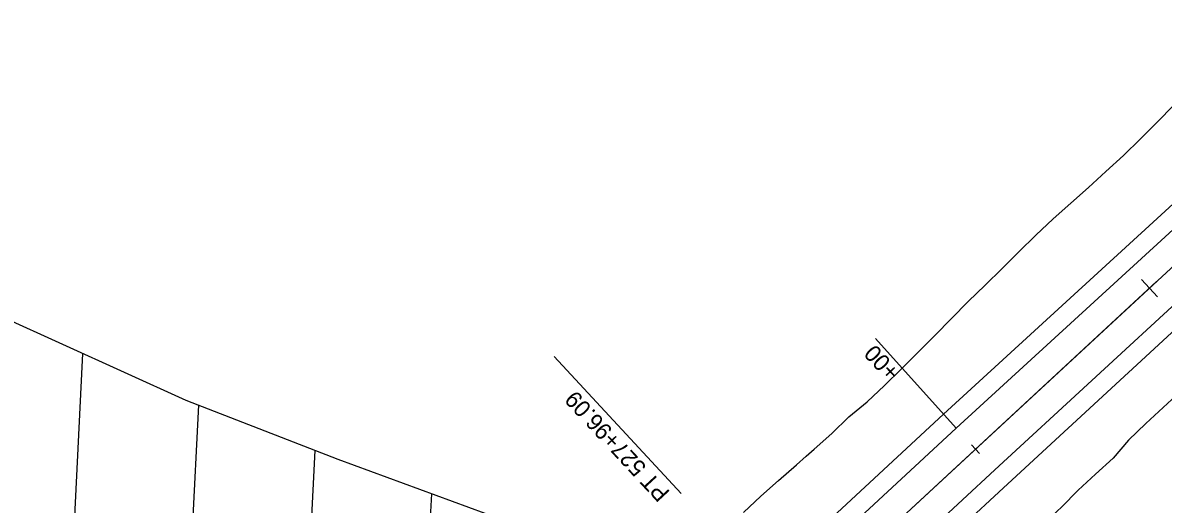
# Model space of a CAD drawing. Extents: x 1300404 to 1323571, y 237813 to 252077.
# Drawn here: x 1311040.8 to 1311522.1, y 242089.5 to 242292.7 of the extents above; entities that cross this region are included whole.
import ezdxf

# ---------------------------------------------------------------- set-up
doc = ezdxf.new("R2010")
doc.units = 0
for name, color, linetype in [('R_Const Limits', 7, 'Continuous'), ('R_Floodway', 7, 'Continuous'), ('R_Horz Alg Annot', 7, 'Continuous'), ('R_Horz Alg Annot Leader', 7, 'Continuous'), ('R_Horz Alg Major Ticks', 7, 'Continuous'), ('R_Horz Alg Minor Ticks', 7, 'Continuous'), ('R_Lane Edge', 7, 'Continuous'), ('R_Proposed', 7, 'Continuous'), ('R_Shoulder', 7, 'Continuous')]:
    doc.layers.add(name, color=color, linetype=linetype)

msp = doc.modelspace()

# ---------------------------------------------------------------- linework, layer by layer
at = {"layer": 'R_Const Limits'}
for points in [[(1311345.07, 242085.98), (1311352.3, 242092.89), (1311359.8, 242099.51), (1311367.33, 242106.09), (1311371.51, 242109.76), (1311374.89, 242112.65), (1311382.3, 242119.36), (1311389.43, 242126.38), (1311397.19, 242132.72), (1311404.48, 242139.57), (1311411.63, 242146.56), (1311418.68, 242153.67), (1311425.77, 242160.72), (1311432.82, 242167.83), (1311439.84, 242174.97), (1311447, 242181.96), (1311454.13, 242188.98), (1311461.27, 242195.98), (1311468.41, 242202.99), (1311475.66, 242209.88), (1311483.09, 242216.57), (1311490.56, 242223.22), (1311497.97, 242229.94), (1311505.4, 242236.63), (1311512.52, 242243.67), (1311519.54, 242250.8), (1311526.59, 242257.9)], [(1311529.44, 242137.05), (1311522.06, 242130.31), (1311514.74, 242123.5), (1311507.54, 242116.56), (1311500.96, 242108.95), (1311493.6, 242102.17), (1311486.31, 242095.33), (1311479.28, 242088.2), (1311471.89, 242081.46), (1311465.07, 242074.11), (1311457.65, 242067.4), (1311450.85, 242060.03), (1311443.97, 242052.74), (1311437.27, 242045.26), (1311434.66, 242041.54), (1311430.29, 242038.08), (1311422.46, 242031.81), (1311413.34, 242026.95), (1311405.41, 242020.79), (1311295.28, 241916.73), (1311295.28, 241916.73)]]:
    msp.add_lwpolyline(points, dxfattribs=at)
at = {"layer": 'R_Floodway'}
for p, q in [((1311041.47, 241659.98), (1311066.18, 242153.15)), ((1311090.32, 241635.77), (1311115.15, 242131.3)), ((1311139.11, 241610.32), (1311164.25, 242112.14)), ((1311187.9, 241584.88), (1311213.4, 242093.9))]:
    msp.add_line(p, q, dxfattribs=at)
msp.add_lwpolyline([(1310379.63, 242680.75), (1310490.18, 242568.72), (1310548.96, 242534.3), (1310676.05, 242414.18), (1310731.56, 242362.99), (1310810.26, 242291.28), (1310887.62, 242241.41), (1310974.87, 242195.88), (1311031.59, 242168.82), (1311109.67, 242133.43), (1311173.76, 242108.43), (1311242.66, 242083.18), (1311339.33, 242032.34), (1311351.04, 242024.49), (1311431.54, 241940.59), (1311405.15, 241750.77), (1311416.02, 241677.63), (1311441.14, 241598.94), (1311547.83, 241506.46), (1311691.44, 241475.03), (1311836.73, 241477.39), (1311974.41, 241472.87)], dxfattribs=at)
at = {"layer": 'R_Horz Alg Annot Leader'}
for points in [[(1311400.69, 242159.47), (1311434.79, 242121.54)], [(1311318.65, 242094.04), (1311265.15, 242151.83)]]:
    msp.add_lwpolyline(points, dxfattribs=at)
at = {"layer": 'R_Horz Alg Major Ticks'}
msp.add_lwpolyline([(1311512.93, 242184.34), (1311519.72, 242177)], dxfattribs=at)
at = {"layer": 'R_Horz Alg Minor Ticks'}
msp.add_lwpolyline([(1311441.24, 242114.57), (1311444.64, 242110.9)], dxfattribs=at)
at = {"layer": 'R_Lane Edge'}
for p, q in [((1311434.79, 242121.54), (1311582.2, 242256.72)), ((1311451.09, 242103.93), (1311598.05, 242239.59)), ((1311434.79, 242121.54), (1311358.53, 242050.95)), ((1311451.09, 242103.93), (1311374.83, 242033.34))]:
    msp.add_line(p, q, dxfattribs=at)
at = {"layer": 'R_Proposed'}
for p, q in [((1311366.68, 242042.15), (1311685.11, 242336.91)), ((1311519.37, 242183.49), (1311366.68, 242042.15)), ((1311366.68, 242042.15), (1311519.37, 242183.49)), ((1311366.68, 242042.15), (1311519.37, 242183.49))]:
    msp.add_line(p, q, dxfattribs=at)
at = {"layer": 'R_Shoulder'}
for p, q in [((1311429.37, 242127.43), (1311576.79, 242262.61)), ((1311456.52, 242098.06), (1311603.48, 242233.71)), ((1311429.37, 242127.43), (1311353.09, 242056.82)), ((1311456.52, 242098.06), (1311380.27, 242027.47))]:
    msp.add_line(p, q, dxfattribs=at)

# ---------------------------------------------------------------- texts
at = {"layer": 'R_Horz Alg Annot'}
for s, rotation, p in [('+00', 133.2183, (1311411.31, 242145.77)), ('PT 527+96.09', 132.7896, (1311314.29, 242094.56))]:
    msp.add_text(s, height=7, rotation=rotation, dxfattribs=at).set_placement(p)

doc.saveas('drawing.dxf')
